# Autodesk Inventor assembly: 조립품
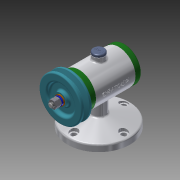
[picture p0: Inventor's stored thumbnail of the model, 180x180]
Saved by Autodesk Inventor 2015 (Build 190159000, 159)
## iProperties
Created: 2018-12
Part Number: 조립품
Document SubType Name: Assembly
Designer: now
Author: now
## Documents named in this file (15)
- C:\Users\now\Desktop\차지철\481207V1068\조립품.iam
- C:\Users\now\Desktop\차지철\481207V1068\V벨트풀리.ipt
- C:\Users\now\Desktop\차지철\481207V1068\고무캡.ipt
- C:\Users\now\Desktop\차지철\481207V1068\너트 M8.ipt
- 너트 M8.ipt
- C:\Users\now\Desktop\차지철\481207V1068\뒤커버.ipt
- C:\Users\now\Desktop\차지철\481207V1068\베어링 15 x 32 x 9.ipt
- C:\Users\now\Desktop\차지철\481207V1068\본체.ipt
- C:\Users\now\Desktop\차지철\481207V1068\볼트 M4 x 12.ipt
- C:\Users\now\Desktop\차지철\481207V1068\스프링와셔 8.ipt
- C:\Users\now\Desktop\차지철\481207V1068\앞커버.ipt
- C:\Users\now\Desktop\차지철\481207V1068\오일 실 15 25 7.ipt
- C:\Users\now\Desktop\차지철\481207V1068\와셔 8x17.ipt
- C:\Users\now\Desktop\차지철\481207V1068\축.ipt
- C:\Users\now\Desktop\차지철\481207V1068\키 3 x 3 x 12.ipt
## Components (2 placed, 2 different names)
1. V벨트풀리:1 — 각도:2
2. 고무캡:1
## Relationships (1: Angle 1)
- 각도:2 [Angle]: V벨트풀리:1
